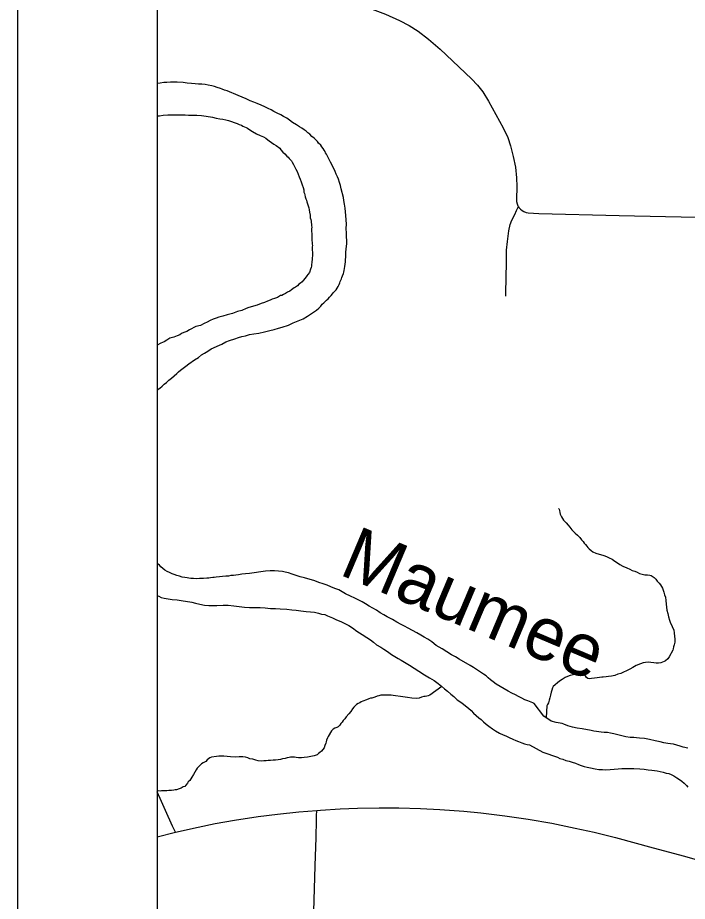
# Model space of a CAD drawing. Extents: x 2.1 to 73.9, y 4 to 26.
# Drawn here: x 41.859 to 42.338, y 20.887 to 21.52 of the extents above; entities that cross this region are included whole.
import ezdxf

# ---------------------------------------------------------------- set-up
doc = ezdxf.new("R2010")
doc.units = 0
for name, color, linetype in [('GM_X_County_Road', 7, 'Continuous'), ('GM_X_Major_River', 7, 'Continuous'), ('GM_X_Major_River_Text', 7, 'Continuous'), ('GM_X_Minor_River', 7, 'Continuous'), ('GM_X_Township_Road', 7, 'Continuous'), ('SH_Data', 7, 'Continuous')]:
    doc.layers.add(name, color=color, linetype=linetype)

msp = doc.modelspace()

# ---------------------------------------------------------------- linework, layer by layer
at = {"layer": 'GM_X_County_Road'}
msp.add_line((41.95853, 20.93332), (41.97153, 20.93659), dxfattribs=at)
for points in [[(41.97153, 20.93659), (41.9879, 20.94037), (42.00009, 20.94286), (42.01389, 20.94526), (42.03079, 20.94785), (42.04467, 20.94966), (42.06014, 20.95127), (42.07287, 20.95232)], [(42.06275, 20.63126), (42.06299, 20.63942), (42.06467, 20.69378), (42.06585, 20.72639), (42.06804, 20.79627), (42.0683, 20.80557), (42.06854, 20.81175), (42.06871, 20.81639), (42.06888, 20.82103), (42.06921, 20.83341), (42.07068, 20.87998), (42.07165, 20.9126), (42.07233, 20.93279), (42.0726, 20.94522), (42.07272, 20.94833), (42.07287, 20.95232)], [(42.07287, 20.95232), (42.07564, 20.95255), (42.08961, 20.95341), (42.10204, 20.9539), (42.11759, 20.95421), (42.13159, 20.95409), (42.14713, 20.95367), (42.16111, 20.95292), (42.17817, 20.95172), (42.19056, 20.95055), (42.20754, 20.94845), (42.22446, 20.94594), (42.24132, 20.94303), (42.2581, 20.93968), (42.27176, 20.93664), (42.28683, 20.9328), (42.31386, 20.92559), (42.33635, 20.91943), (42.35279, 20.91478), (42.37084, 20.91012), (42.38293, 20.90728), (42.38806, 20.90622)]]:
    msp.add_lwpolyline(points, dxfattribs=at)
at = {"layer": 'GM_X_Major_River'}
for points in [[(42.09371, 21.34835), (42.09374, 21.34987), (42.09379, 21.35196), (42.09403, 21.35424), (42.09427, 21.35632), (42.09431, 21.35803), (42.09436, 21.36012), (42.09424, 21.36317), (42.0941, 21.36564), (42.09398, 21.36888), (42.09406, 21.37211), (42.09394, 21.37515), (42.09382, 21.3782), (42.09349, 21.38087), (42.09317, 21.38353), (42.09286, 21.38639), (42.09235, 21.38907), (42.09201, 21.39117), (42.09044, 21.39729), (42.08992, 21.39977), (42.08921, 21.40188), (42.0885, 21.40417), (42.08778, 21.4059), (42.08687, 21.40782), (42.08596, 21.40975), (42.08523, 21.41147), (42.08432, 21.41301), (42.08359, 21.41474), (42.08268, 21.41647), (42.08195, 21.41782), (42.08122, 21.41936), (42.08049, 21.42071), (42.07976, 21.42205), (42.07921, 21.42321), (42.07885, 21.42416), (42.07811, 21.42513), (42.07738, 21.42629), (42.07645, 21.42745), (42.07572, 21.42861), (42.07422, 21.42997), (42.0733, 21.43133), (42.07218, 21.43249), (42.07107, 21.43366), (42.06938, 21.43484), (42.06789, 21.43639), (42.06658, 21.43756), (42.06528, 21.43873), (42.06396, 21.43952), (42.06227, 21.4407), (42.06039, 21.4417), (42.05832, 21.44307), (42.05551, 21.44485), (42.05326, 21.44642), (42.05139, 21.44798), (42.04913, 21.44918), (42.04706, 21.45036), (42.04461, 21.45156), (42.04216, 21.45276), (42.04009, 21.45395), (42.03802, 21.45494), (42.03556, 21.45595), (42.03292, 21.45715), (42.03009, 21.45836), (42.02783, 21.45936), (42.02518, 21.46037), (42.02236, 21.46176), (42.01934, 21.46297), (42.01651, 21.46418), (42.00858, 21.4674), (42.00669, 21.46802), (42.00517, 21.46862), (42.00385, 21.46922), (42.00158, 21.46984), (41.99969, 21.47065), (41.99761, 21.47107), (41.99514, 21.47151), (41.99287, 21.47194), (41.99058, 21.47218), (41.98811, 21.47224), (41.98564, 21.47249), (41.98317, 21.47273), (41.98012, 21.47299), (41.97708, 21.47344), (41.9729, 21.47373), (41.97023, 21.47379), (41.96794, 21.47365), (41.96546, 21.47352), (41.96317, 21.47338), (41.96069, 21.47306), (41.95859, 21.47272), (41.95853, 21.47271)], [(41.95853, 21.44952), (41.96016, 21.44968), (41.96283, 21.45), (41.96608, 21.45031), (41.96856, 21.45044), (41.97104, 21.45039), (41.97351, 21.45033), (41.9758, 21.45028), (41.97846, 21.45022), (41.98094, 21.45016), (41.9838, 21.4501), (41.98703, 21.45002), (41.99026, 21.44976), (41.99369, 21.4493)], [(41.99369, 21.4493), (41.99805, 21.44863), (42.0009, 21.448), (42.00336, 21.44756), (42.00545, 21.44713), (42.00773, 21.4467), (42.00962, 21.44628), (42.0117, 21.44566), (42.01378, 21.44485), (42.01586, 21.44423), (42.01737, 21.44344), (42.01888, 21.44283), (42.02001, 21.44224), (42.02114, 21.44183), (42.02227, 21.44123), (42.02322, 21.44083), (42.0249, 21.43965), (42.02678, 21.43828), (42.0296, 21.4367), (42.03243, 21.43549), (42.03469, 21.43449), (42.03639, 21.43369), (42.03789, 21.43251), (42.03882, 21.43173), (42.04032, 21.43056), (42.0422, 21.42937), (42.04389, 21.42838), (42.04632, 21.42643), (42.04706, 21.42527), (42.04855, 21.42371), (42.05004, 21.42235), (42.05134, 21.4208), (42.05228, 21.42002), (42.05321, 21.41905), (42.05469, 21.4173), (42.05524, 21.41634), (42.05616, 21.4148), (42.05689, 21.41326), (42.0578, 21.41153), (42.05871, 21.4098), (42.05943, 21.40788), (42.06015, 21.40596), (42.06106, 21.40423), (42.06159, 21.40232), (42.06231, 21.40021), (42.06302, 21.39829), (42.06356, 21.39657), (42.06371, 21.39504), (42.06407, 21.39389), (42.06443, 21.39294), (42.06459, 21.3916), (42.06494, 21.39026), (42.06549, 21.3893), (42.06584, 21.38796), (42.06619, 21.38662), (42.06673, 21.38528), (42.06708, 21.38375), (42.06742, 21.38222), (42.06777, 21.38069), (42.0681, 21.37859), (42.06825, 21.37669), (42.0686, 21.37535), (42.06876, 21.37421), (42.06893, 21.37325), (42.0691, 21.37211), (42.06907, 21.37097), (42.06924, 21.36982), (42.06921, 21.36868), (42.069, 21.36774), (42.06917, 21.36678), (42.06933, 21.36545), (42.0693, 21.36431), (42.06923, 21.36127), (42.0694, 21.36031), (42.06956, 21.35898), (42.06954, 21.35784), (42.0697, 21.3567), (42.06968, 21.35575), (42.06965, 21.35441), (42.06963, 21.35346), (42.06978, 21.35194), (42.06976, 21.3508), (42.06972, 21.34928), (42.06969, 21.34795), (42.06947, 21.34662), (42.06944, 21.34529), (42.06942, 21.34434), (42.06921, 21.3434), (42.06899, 21.34207), (42.06877, 21.34094), (42.06836, 21.33981), (42.06774, 21.33754), (42.06637, 21.33605), (42.06578, 21.33511), (42.0646, 21.33343), (42.06323, 21.33175), (42.06244, 21.33082), (42.06128, 21.32989), (42.06012, 21.32897), (42.05895, 21.32785), (42.05759, 21.32693)], [(41.95853, 21.25345), (41.9603, 21.25463), (41.96205, 21.25611), (41.96341, 21.25741), (41.96516, 21.2587), (41.96691, 21.26037), (41.96866, 21.26186), (41.97079, 21.26333), (41.97255, 21.26519), (41.97371, 21.2663), (41.97526, 21.26741), (41.9772, 21.26888), (41.97895, 21.27037), (41.98127, 21.27202), (41.98515, 21.27479), (41.98805, 21.27662), (41.99038, 21.27847), (41.9925, 21.27975), (41.99482, 21.28122), (41.99714, 21.28269), (41.99888, 21.2836), (42.00157, 21.28468), (42.00484, 21.28612), (42.00774, 21.28777), (42.01043, 21.28885), (42.01426, 21.2899), (42.01676, 21.29098), (42.01907, 21.29169), (42.02174, 21.2922), (42.02462, 21.29309), (42.02768, 21.29359), (42.03131, 21.29407), (42.03553, 21.29493), (42.03917, 21.29599), (42.04242, 21.29667), (42.04549, 21.29755), (42.04818, 21.29825), (42.05259, 21.29967), (42.05606, 21.3013), (42.05952, 21.30275), (42.06318, 21.30437), (42.06627, 21.30621), (42.07265, 21.31043), (42.0744, 21.31191), (42.07577, 21.3134), (42.07675, 21.31471), (42.07791, 21.31564), (42.07889, 21.31675), (42.07987, 21.31768), (42.08103, 21.31861), (42.08201, 21.31972), (42.08318, 21.32103), (42.08416, 21.32215), (42.08494, 21.32308), (42.08592, 21.32401), (42.0867, 21.32513), (42.08749, 21.32625), (42.08809, 21.32738), (42.08888, 21.32888), (42.08929, 21.33001), (42.08969, 21.33096), (42.0901, 21.3319), (42.0905, 21.33284), (42.0909, 21.33397), (42.09131, 21.3351), (42.09192, 21.3368), (42.09232, 21.33774), (42.09254, 21.33887), (42.09276, 21.3402), (42.09299, 21.34172), (42.09322, 21.34342), (42.09344, 21.34513), (42.09348, 21.34684), (42.09371, 21.34835)], [(42.05759, 21.32693), (42.05663, 21.32639), (42.05566, 21.32584), (42.05469, 21.32491), (42.05352, 21.32399), (42.05179, 21.32327), (42.05044, 21.32234), (42.04909, 21.32162), (42.04774, 21.32108), (42.04678, 21.32091), (42.04485, 21.31962), (42.04255, 21.31891), (42.04101, 21.31838), (42.03947, 21.31765), (42.03755, 21.31694), (42.03543, 21.31603), (42.03294, 21.31514), (42.03005, 21.31407), (42.0243, 21.3123), (42.02238, 21.31158), (42.01911, 21.31032), (42.01604, 21.30944), (42.01258, 21.30819), (42.00875, 21.30714), (42.00549, 21.30626), (42.0028, 21.30556), (42.00069, 21.30466), (41.99858, 21.30395), (41.99646, 21.30304), (41.99434, 21.30195), (41.99222, 21.30086), (41.98952, 21.2994), (41.98626, 21.29871), (41.98472, 21.29799), (41.98318, 21.29707), (41.98164, 21.29635), (41.97971, 21.29525), (41.97759, 21.29454), (41.97605, 21.29382), (41.9747, 21.29289), (41.97277, 21.29199), (41.97047, 21.29109), (41.96855, 21.29056), (41.96759, 21.2904), (41.96546, 21.28892), (41.96353, 21.28783), (41.96122, 21.28674), (41.95853, 21.28529)], [(42.10299, 21.1029), (42.10017, 21.1043), (42.09715, 21.1057), (42.09357, 21.1073), (42.09113, 21.10888), (42.08868, 21.11027), (42.08585, 21.11128), (42.08302, 21.11248), (42.08037, 21.1135), (42.07754, 21.11451), (42.07432, 21.11553), (42.07149, 21.11655), (42.06903, 21.11737), (42.06656, 21.11799), (42.06411, 21.11881), (42.06089, 21.11964), (42.05805, 21.12047), (42.05521, 21.12148), (42.05256, 21.1223), (42.05029, 21.12293), (42.0482, 21.12335), (42.04554, 21.12361), (42.0425, 21.12386), (42.03945, 21.12393), (42.03621, 21.12363), (42.02474, 21.12199), (42.02187, 21.12167), (42.0192, 21.12136), (42.0169, 21.12103), (42.01499, 21.12069), (42.01327, 21.12054), (42.01136, 21.12039), (42.00964, 21.12005), (42.00773, 21.11991), (42.00544, 21.11977), (42.00315, 21.11944), (42.00086, 21.1193), (41.99933, 21.11915), (41.99838, 21.11898), (41.99666, 21.11883), (41.99551, 21.11866), (41.99398, 21.11851), (41.99169, 21.11837), (41.98883, 21.11825), (41.98654, 21.11811), (41.98445, 21.11835), (41.98274, 21.11838), (41.98122, 21.11861), (41.97989, 21.11883), (41.97837, 21.11905), (41.97647, 21.11929), (41.97458, 21.1199), (41.9725, 21.12052), (41.9708, 21.12113), (41.96929, 21.12173), (41.9674, 21.12254), (41.9657, 21.12334), (41.96401, 21.12432), (41.96251, 21.1255), (41.96121, 21.12667), (41.96009, 21.12784), (41.95915, 21.12862), (41.95853, 21.12895)], [(41.95853, 21.10608), (41.95958, 21.1056), (41.96128, 21.10481), (41.96355, 21.10418), (41.9664, 21.10374), (41.96925, 21.10329), (41.97286, 21.10302), (41.97571, 21.10258), (41.98331, 21.10145), (41.98596, 21.10063), (41.98899, 21.09999), (41.9924, 21.09934), (41.99545, 21.09908), (41.99811, 21.09902), (42.00135, 21.09895), (42.00574, 21.09923), (42.00936, 21.09915), (42.01335, 21.09868), (42.01734, 21.0982), (42.02114, 21.09774), (42.02476, 21.09766), (42.02837, 21.09757), (42.03237, 21.09748), (42.03599, 21.09721), (42.03979, 21.09693), (42.04322, 21.09685), (42.04664, 21.09659), (42.0514, 21.09629), (42.05501, 21.09582), (42.05805, 21.09557), (42.06147, 21.09511), (42.06527, 21.09464), (42.0685, 21.09437), (42.07136, 21.09412), (42.07401, 21.09349), (42.07628, 21.09287), (42.07856, 21.09244), (42.08064, 21.09163), (42.08403, 21.09022), (42.08705, 21.08882), (42.09007, 21.08761), (42.09308, 21.08602), (42.09591, 21.08462), (42.09854, 21.08304), (42.10154, 21.0807), (42.10529, 21.07814), (42.10867, 21.07597), (42.11149, 21.07438)], [(42.23556, 21.01987), (42.22859, 21.02894), (42.22765, 21.02934), (42.22651, 21.02975), (42.22538, 21.03015), (42.22406, 21.03075), (42.22198, 21.03156), (42.21991, 21.03275), (42.21746, 21.03395), (42.2152, 21.03514), (42.21275, 21.03633), (42.20993, 21.03773), (42.20711, 21.03931), (42.20428, 21.0409), (42.20146, 21.04268), (42.19921, 21.04425), (42.19734, 21.04581), (42.19566, 21.04718), (42.19417, 21.04855), (42.19229, 21.04973), (42.18948, 21.05169), (42.18741, 21.05307), (42.18516, 21.05464), (42.18272, 21.05603), (42.17482, 21.06058), (42.17219, 21.06216), (42.16936, 21.06375), (42.16617, 21.06572), (42.16279, 21.06808), (42.15846, 21.07046), (42.15528, 21.073), (42.15247, 21.07478), (42.14983, 21.07636), (42.14739, 21.07775), (42.14457, 21.07933), (42.14137, 21.08112), (42.13836, 21.08271), (42.13572, 21.08429), (42.13327, 21.08548), (42.13026, 21.08707), (42.12706, 21.08886), (42.1233, 21.09084), (42.12085, 21.09223), (42.11841, 21.09381), (42.11559, 21.09558), (42.11296, 21.09716), (42.11033, 21.09855), (42.10789, 21.10013), (42.10544, 21.10171), (42.10299, 21.1029)], [(42.11149, 21.07438), (42.11355, 21.07282), (42.1156, 21.07087), (42.11881, 21.06928), (42.12087, 21.06771), (42.12275, 21.06652), (42.12462, 21.06534), (42.1265, 21.06397), (42.12875, 21.06239), (42.13119, 21.06101), (42.13326, 21.05982), (42.13928, 21.05626), (42.14266, 21.05409), (42.14604, 21.05192), (42.14998, 21.04936), (42.15374, 21.04719), (42.15694, 21.04521), (42.15975, 21.04306), (42.16218, 21.04129), (42.16443, 21.03934), (42.16648, 21.03758), (42.16891, 21.03562), (42.17116, 21.03386), (42.17339, 21.03134), (42.17677, 21.02936), (42.17939, 21.02721), (42.18164, 21.02545), (42.18351, 21.0237), (42.18518, 21.02195), (42.18705, 21.02019), (42.18892, 21.01863), (42.1906, 21.01726), (42.19228, 21.0157), (42.19434, 21.01413), (42.19621, 21.01257), (42.19884, 21.0108), (42.2009, 21.00923), (42.20372, 21.00764), (42.20636, 21.00644), (42.20844, 21.00564), (42.21069, 21.00444), (42.21333, 21.00324), (42.2156, 21.00243), (42.21749, 21.00163), (42.21975, 21.00062), (42.22184, 21.00001), (42.22354, 20.9994), (42.22525, 20.99917), (42.23496, 20.99396)], [(42.33871, 20.99675), (42.3355, 20.99758), (42.33323, 20.99839), (42.33078, 20.99902), (42.32851, 20.99964), (42.32643, 21.00006), (42.32434, 21.0003), (42.32169, 21.00074), (42.31885, 21.00137), (42.31526, 21.00202), (42.31129, 21.00306), (42.30769, 21.00371), (42.30408, 21.00398), (42.302, 21.00422), (42.3001, 21.00445), (42.29744, 21.00451), (42.29441, 21.00496), (42.29139, 21.00579), (42.28855, 21.00642), (42.28571, 21.00706), (42.28325, 21.00768), (42.28117, 21.00811), (42.27889, 21.00816), (42.27662, 21.0084), (42.27339, 21.00885), (42.27131, 21.00909), (42.26942, 21.00951), (42.26298, 21.01061), (42.25957, 21.01125), (42.25616, 21.0119), (42.25276, 21.01292), (42.24994, 21.01394), (42.24862, 21.01454), (42.24729, 21.01476), (42.24445, 21.0152), (42.24086, 21.01623), (42.23556, 21.01987)], [(42.23496, 20.99396), (42.24541, 20.99029)], [(42.24541, 20.99029), (42.2471, 20.9895), (42.24918, 20.98888), (42.25145, 20.98807), (42.25371, 20.98745), (42.25598, 20.98683), (42.25824, 20.98602), (42.26032, 20.98521), (42.26239, 20.9844), (42.26447, 20.98379), (42.26655, 20.98336), (42.26901, 20.98273), (42.27241, 20.98209), (42.27507, 20.98165), (42.27754, 20.98159), (42.28, 20.98135), (42.28305, 20.98147), (42.2861, 20.98178), (42.28895, 20.9821), (42.29143, 20.98223), (42.29409, 20.98236), (42.29675, 20.9823), (42.29998, 20.98223), (42.30435, 20.98213), (42.30758, 20.98187), (42.31042, 20.98143), (42.31288, 20.98099), (42.31478, 20.98076), (42.31686, 20.98052), (42.31895, 20.9801), (42.32103, 20.97967), (42.32329, 20.97905), (42.32519, 20.97863), (42.32688, 20.97802), (42.32876, 20.97703), (42.33101, 20.97565), (42.33289, 20.97446), (42.33457, 20.97329), (42.33625, 20.97173), (42.33773, 20.97018), (42.33885, 20.96901)]]:
    msp.add_lwpolyline(points, dxfattribs=at)
at = {"layer": 'GM_X_Minor_River'}
for points in [[(42.24618, 21.16846), (42.24655, 21.16788), (42.24671, 21.16693), (42.24706, 21.16559), (42.24723, 21.16445), (42.24814, 21.16253), (42.24887, 21.16118), (42.24961, 21.16021), (42.25053, 21.15924), (42.25165, 21.15808), (42.25294, 21.15653), (42.25424, 21.15517), (42.25572, 21.15324), (42.25795, 21.15091), (42.25963, 21.14935), (42.2613, 21.14779), (42.2626, 21.14605), (42.26371, 21.14489), (42.26444, 21.14373), (42.26537, 21.14257), (42.2663, 21.1416), (42.26704, 21.14064), (42.26816, 21.13966), (42.26946, 21.13849), (42.27076, 21.13732), (42.27284, 21.13652), (42.2785, 21.13487), (42.28039, 21.13407), (42.28246, 21.13307), (42.28453, 21.13208), (42.28639, 21.13071), (42.28827, 21.12952), (42.29014, 21.12834), (42.29221, 21.12716), (42.29503, 21.12595), (42.2971, 21.12496), (42.29899, 21.12415), (42.30068, 21.12355), (42.30238, 21.12275), (42.30426, 21.12195), (42.30615, 21.12133), (42.30804, 21.12091), (42.30994, 21.12087), (42.31145, 21.12064), (42.31259, 21.12043), (42.31465, 21.11905), (42.31576, 21.11789), (42.31687, 21.11653), (42.31817, 21.11499), (42.31929, 21.11382), (42.31983, 21.11267), (42.32056, 21.11132), (42.3211, 21.10998), (42.32164, 21.10864), (42.32217, 21.10673), (42.3227, 21.10501), (42.32302, 21.10253), (42.32335, 21.10005), (42.32349, 21.09777), (42.32382, 21.09567), (42.32434, 21.09338), (42.32504, 21.0909), (42.32575, 21.08841), (42.32646, 21.0863), (42.32737, 21.08458), (42.32791, 21.08323), (42.32864, 21.08151), (42.32896, 21.07922), (42.32929, 21.07693), (42.32944, 21.07484), (42.32939, 21.07275), (42.32897, 21.07086), (42.32855, 21.06935), (42.32833, 21.06803), (42.32793, 21.06709), (42.32535, 21.06221), (42.32437, 21.06071), (42.32282, 21.05941), (42.32185, 21.05886), (42.31936, 21.05797), (42.31764, 21.05763), (42.31612, 21.05766), (42.31442, 21.05789), (42.31233, 21.05813), (42.31044, 21.05836), (42.30853, 21.05821), (42.30681, 21.05787), (42.3049, 21.05715), (42.30183, 21.05608), (42.29933, 21.05462), (42.29721, 21.05334), (42.29471, 21.05225), (42.29259, 21.05116), (42.29067, 21.05026), (42.28857, 21.04973), (42.28646, 21.04883), (42.28398, 21.04851), (42.28188, 21.04817), (42.28016, 21.04783), (42.27807, 21.04769), (42.27712, 21.04771)], [(42.27712, 21.04771), (42.27559, 21.04755), (42.27369, 21.04722), (42.27178, 21.04688), (42.26968, 21.04674), (42.26797, 21.04659), (42.26702, 21.0468), (42.26608, 21.04739), (42.26535, 21.04873), (42.26404, 21.04933), (42.2631, 21.04992), (42.26178, 21.05033), (42.26006, 21.05018), (42.25873, 21.04983), (42.25662, 21.04931), (42.25452, 21.04898), (42.2526, 21.04807), (42.25087, 21.04735), (42.24875, 21.04607), (42.24683, 21.04478), (42.24218, 21.04089), (42.24177, 21.03995), (42.24136, 21.03844), (42.24095, 21.03693), (42.24033, 21.03486), (42.2399, 21.03278), (42.2393, 21.03127), (42.23888, 21.02938), (42.23828, 21.02807), (42.23768, 21.02713), (42.23717, 21.01876)], [(42.16258, 21.04095), (42.15384, 21.03483), (42.15269, 21.03428), (42.15173, 21.03411), (42.15059, 21.03395), (42.14963, 21.03378), (42.1479, 21.03325), (42.14637, 21.03272), (42.14445, 21.03238), (42.14103, 21.03265), (42.1378, 21.0331), (42.13457, 21.03356), (42.12755, 21.03467), (42.12621, 21.0347), (42.12469, 21.03473), (42.12317, 21.03477), (42.12183, 21.0348), (42.12031, 21.03483), (42.11878, 21.03468), (42.11725, 21.03433), (42.1161, 21.03398), (42.11437, 21.03326), (42.11245, 21.03273), (42.1113, 21.03257), (42.11015, 21.03221), (42.10842, 21.03149), (42.10592, 21.03041), (42.10477, 21.03005), (42.1038, 21.02932), (42.10245, 21.02878), (42.10129, 21.02804), (42.09954, 21.02618), (42.09837, 21.02507), (42.09718, 21.02319), (42.09581, 21.02132), (42.09405, 21.01927), (42.09306, 21.01796), (42.09189, 21.01666), (42.0911, 21.01554), (42.09012, 21.01442), (42.08934, 21.0133), (42.08817, 21.01218), (42.0872, 21.01163), (42.08586, 21.01109), (42.0847, 21.01055), (42.08334, 21.00925), (42.08096, 21.00531), (42.08056, 21.00418), (42.07995, 21.00267), (42.07954, 21.00135), (42.07933, 21.00041), (42.07872, 20.99871), (42.07811, 20.9972), (42.07713, 20.99589), (42.07615, 20.99459), (42.07518, 20.99385), (42.07421, 20.99311), (42.07323, 20.99199), (42.07093, 20.99128), (42.06863, 20.99077), (42.06633, 20.99044), (42.06385, 20.99011), (42.06194, 20.98997), (42.05985, 20.99002), (42.05814, 20.99025), (42.05681, 20.99047), (42.05548, 20.9905), (42.05395, 20.99034), (42.05299, 20.99017), (42.05165, 20.98982), (42.05012, 20.98948), (42.04839, 20.98914), (42.04686, 20.98879), (42.04514, 20.98845), (42.04342, 20.9883), (42.0417, 20.98815), (42.0398, 20.988), (42.03808, 20.98804), (42.03655, 20.98789), (42.03483, 20.98773), (42.03312, 20.98758), (42.03083, 20.98783), (42.02913, 20.98825), (42.02705, 20.98886), (42.02496, 20.98929), (42.02345, 20.98989), (42.02175, 20.9905), (42.01985, 20.99074), (42.01737, 20.9906), (42.01432, 20.99048), (42.01108, 20.99056), (42.00861, 20.9908), (42.00633, 20.99105), (42.00462, 20.99109), (42.00271, 20.99113), (42.00099, 20.99098), (41.99755, 20.99049), (41.99621, 20.98995), (41.99427, 20.98847), (41.99329, 20.98735), (41.99155, 20.98644)], [(41.99155, 20.98644), (41.9902, 20.98552), (41.98923, 20.98478), (41.98844, 20.98366), (41.98727, 20.98255), (41.98648, 20.98123), (41.98549, 20.97974), (41.9845, 20.97805), (41.98331, 20.97598), (41.98193, 20.97373), (41.98076, 20.97262), (41.98017, 20.97168), (41.97899, 20.97038), (41.97821, 20.96945), (41.97706, 20.96909), (41.97571, 20.96817), (41.97436, 20.96763), (41.97244, 20.96711), (41.9713, 20.96694), (41.97034, 20.96677), (41.96881, 20.96662), (41.9669, 20.96647), (41.96537, 20.96632), (41.96404, 20.96635), (41.96271, 20.96638), (41.96156, 20.96621), (41.96061, 20.96604), (41.95966, 20.96626), (41.95853, 20.966)]]:
    msp.add_lwpolyline(points, dxfattribs=at)
at = {"layer": 'GM_X_Township_Road'}
for points in [[(42.09157, 21.53364), (42.10182, 21.53006), (42.12216, 21.52234), (42.1321, 21.51793), (42.13899, 21.51434), (42.14557, 21.51021), (42.15301, 21.50459), (42.16119, 21.49743), (42.18385, 21.47615), (42.18812, 21.47163), (42.19195, 21.46674), (42.19604, 21.46014), (42.20643, 21.44102), (42.20972, 21.43399), (42.21177, 21.42812), (42.21373, 21.4206), (42.21519, 21.41297), (42.21603, 21.40525), (42.21616, 21.39904), (42.21595, 21.38972), (42.21604, 21.38817), (42.21636, 21.38665), (42.21694, 21.38521), (42.21732, 21.3846)], [(42.20824, 21.32047), (42.20828, 21.32204), (42.20865, 21.33456), (42.20877, 21.34395), (42.20895, 21.35333), (42.2095, 21.35957), (42.21046, 21.36734), (42.21151, 21.37191), (42.21264, 21.37483), (42.21481, 21.37899), (42.21608, 21.38184), (42.21732, 21.3846)], [(42.21732, 21.3846), (42.21776, 21.38389), (42.21879, 21.38274), (42.22001, 21.38178), (42.22136, 21.38102), (42.22282, 21.38046), (42.22433, 21.38009), (42.23208, 21.37964), (42.28957, 21.37831), (42.36725, 21.37661), (42.42878, 21.3752), (42.457, 21.37443), (42.47562, 21.37392), (42.49576, 21.37351), (42.51907, 21.37321), (42.53613, 21.37261), (42.56097, 21.37194), (42.59213, 21.37117)], [(41.97153, 20.93659), (41.96957, 20.94094), (41.96447, 20.95225), (41.96067, 20.96076), (41.95853, 20.96549)]]:
    msp.add_lwpolyline(points, dxfattribs=at)
at = {"layer": 'SH_Data'}
for p, q in [((41.85853, 25.00511), (41.85853, 18.00511)), ((41.95853, 24.90511), (41.95853, 18.10511))]:
    msp.add_line(p, q, dxfattribs=at)

# ---------------------------------------------------------------- texts
at = {"layer": 'GM_X_Major_River_Text'}
msp.add_text('Maumee', height=0.037898, rotation=337.05076, dxfattribs=at).set_placement((42.0879, 21.12161))

doc.saveas('drawing.dxf')
